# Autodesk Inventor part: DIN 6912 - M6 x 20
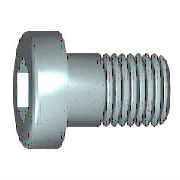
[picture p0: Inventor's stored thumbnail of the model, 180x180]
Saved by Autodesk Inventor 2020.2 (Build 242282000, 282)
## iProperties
Manager: www.cadconsulting.pl
Company: Fabian Stasiak CAD Consulting
IsCustomPart: 0
Created: 2010-02
Part Number: DIN 6912 - M6 x 20
Material: Stal, miękka
Description: Wkręt z łbem półkolistym walcowym
Document SubType Name: Modeling
Standard: DIN 6912
Designer: F.Stasiak
Standard Revision: 1985
Standards Organization: DIN
Language: pl-PL
Size Designation: M6 x 20
Categories: <MemberInstance><Categories><Category DisplayName="Mocowania" InternalName="e4da775c-781d-43d5-af7c-5136215cf5a6" Mnemonic="FSTN"><Category DisplayName="Śruby"
Density: 1 g/cm^3
Appearance: Stal
Author: F.Stasiak
Subject: Zbiór ćwiczeń. Autodesk Inventor 2020. Kurs podstawowy
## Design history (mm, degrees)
body "Solid1"
sketch "Sketch1"
  geometry: L1 (1.866, 0)-(20, 0); L2 (20, 0)-(20, 3); L3 (20, 3)-(0, 3); L4 (0, 3)-(0, 5); L5 (0, 5)-(-4, 5); L6 (-4, 5)-(-4, 2.887); L7 (-4, 2.887)-(-1.5, 2.887); L8 (-1.5, 2.887)-(-0.699, 1.5); L9 (-8.8, 0)-(24.8, 0) reference; L10 (0, -1)-(0, 6) reference; L11 (-0.699, 1.5)-(1, 1.5); L12 (1, 1.5)-(1.866, 0); L13 (-4, 2.887)-(-4, 0); L14 (-4, 4.4)-(-3.4, 5)
  constraints: 24 end point, 6 parallel, 5 point on line, 3 perpendicular, 2 collinear, 1 horizontal
  dimensions: "d0" = 4 distance between parallel lines of L6 L4 (= KOH); "d1" = 2.5 distance of L6.end L7.end (= INTI); "d2" = 60 deg angle of L8 L1; "d3" = 6 diameter of L3 L1 (= GD); "d4" = 5.7735 diameter of L7 L1 (= 1.1547 x SW); "d5" = 10 diameter of L5 L1 (= KOD); "d15" = 5 distance from line of L11.end L6 (= INFT); "d16" = 3 diameter of L11 L1 (= SDT); "d17" = 20 distance between parallel lines of L4 L2 (= NLG); "d32" = 45 deg angle of L14 L5; "d33" = 0.6 distance of L14.end L5.end (= Cham)
revolve "Body" stored, may be unused: angle "d10" = 90 deg
revolve "Chamfer2" stored, may be unused: angle "d34" = 90 deg
sketch "Sketch2"
  geometry: L1 (0, -7)-(0, 7) reference; L2 (-7, 0)-(7, 0) reference; L3 (2.887, 0)-(1.443, -2.5); L4 (1.443, -2.5)-(-1.443, -2.5); L5 (-1.443, -2.5)-(-2.887, 0); L6 (-2.887, 0)-(-1.443, 2.5); L7 (-1.443, 2.5)-(1.443, 2.5); L8 (1.443, 2.5)-(2.887, 0); 2 further points
  constraints: 12 end point, 1 coincident, 1 horizontal alignment, 1 point on line, 12 other
extrude "Slot" join sketch "Sketch2" taper "d6" = 0 deg; stored distance "d11" = 10
feature "Thread" dims "d7" = 14.5 (= GEL), "d8" = 0
chamfer "Chamfer1" distance "d9" = 0.61345 (= -0.5 x SPD + 0.5 x GD); stored, may be unused: second distance "d12" = 0.61345 (= GUL), angle "d28" = 45 deg
workaxis "Work Axis1"
workplane "Work Plane1"
other parameters: "GD" = 6 (= NND) [user parameter; used in 2 equation terms], "NLG" = 20 [user parameter; used in 1 equation term], "GEL" = 14.5 [user parameter; used in 1 equation term], "KOD" = 10 [user parameter; used in 1 equation term], "KOH" = 4 [user parameter; used in 1 equation term], "GUL" = 0.61345 (= 0.61345 x PTC) [user parameter; used in 1 equation term], "SW" = 5 [user parameter; used in 2 equation terms], "INTI" = 2.5 [user parameter; used in 1 equation term], "SPD" = 4.7731 (= NND - 1.2269 x PTC) [user parameter; used in 1 equation term], "d14" = 0, "SDT" = 3 [user parameter; used in 1 equation term], "INFT" = 5 [user parameter; used in 1 equation term], "d30" = 0, "d31" = 0, "Cham" = 0.6 [user parameter; used in 1 equation term], "TOA" = 30 deg [user parameter], "GD1" = 4.7731 (= THREADDIA - 1.2269 x PTC) [user parameter], "THREADDIA" = 6 [user parameter; used in 1 equation term], "BDM" = 6 (= NND) [user parameter], "FAWI" = 45 deg [user parameter], "RR" = 0.6 (= 0.1 x NND) [user parameter], "PTC" = 1 [user parameter; used in 5 equation terms], "NND" = 6 [user parameter; used in 4 equation terms], "FAWI1" = 45 deg [user parameter], "GAL" = 0.61345 (= 0.61345 x PTC) [user parameter], "E0" = 5.775 (= 1.155 x SW) [user parameter]
